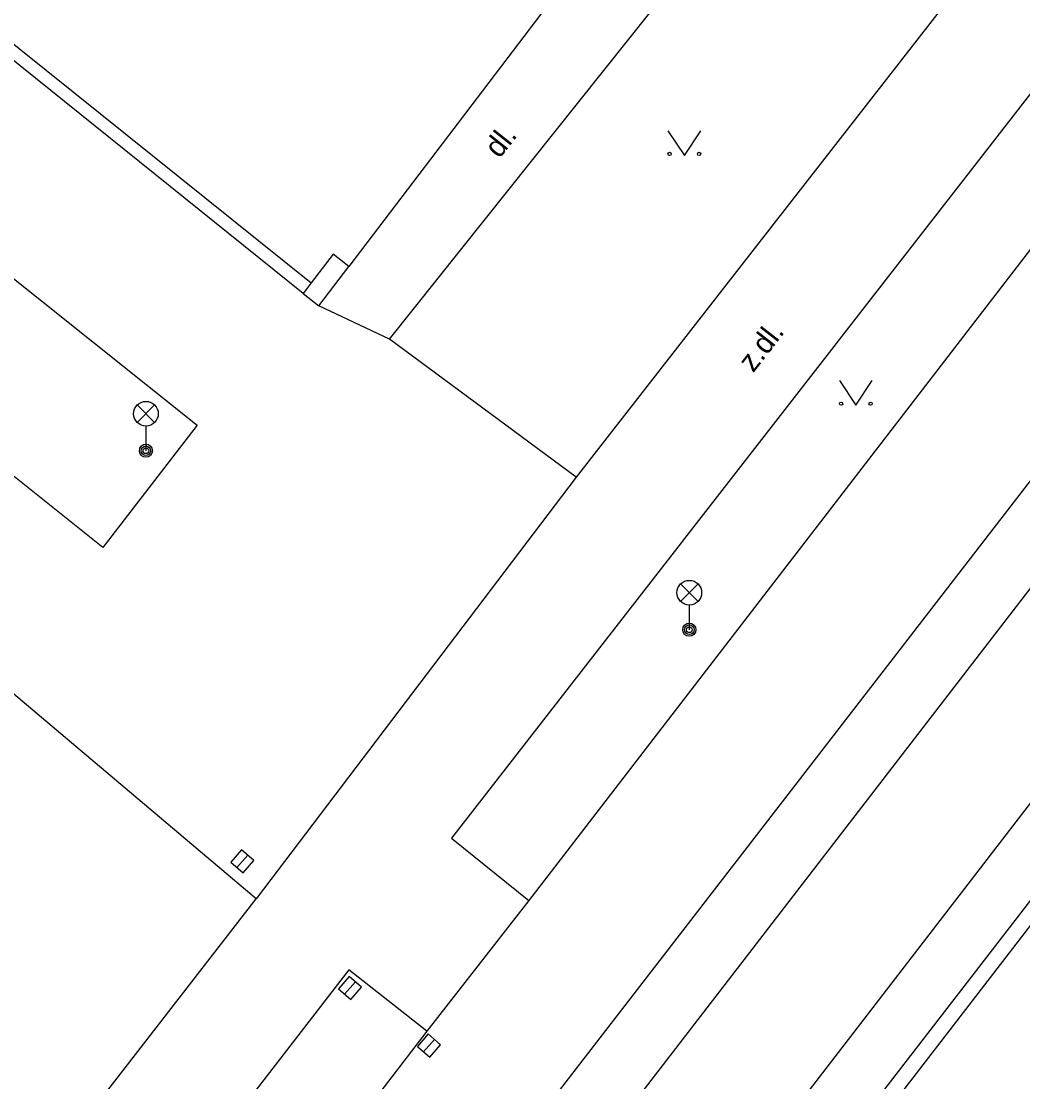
# Model space of a CAD drawing. Extents: x -598932 to -598196, y -1162207 to -1161504.
# Drawn here: x -598777.34 to -598746.91, y -1161970.82 to -1161938.58 of the extents above; entities that cross this region are included whole.
import ezdxf

# ---------------------------------------------------------------- set-up
doc = ezdxf.new("R2010")
doc.units = 0
for name, color, linetype in [('Level 27', 7, 'Continuous'), ('Level 33', 7, 'Continuous'), ('Level 36', 7, 'Continuous'), ('TM - chodniky - VP', 7, 'Continuous'), ('TM - komunikace - VP', 7, 'Continuous'), ('TM - MHD - osa koleji', 7, 'Continuous'), ('TM - popis povrchu', 7, 'Continuous'), ('TM - rozhrani ploch obecne - VP', 7, 'Continuous'), ('TM - zabradli - VP', 7, 'Continuous')]:
    doc.layers.add(name, color=color, linetype=linetype)

msp = doc.modelspace()

# ---------------------------------------------------------------- linework, layer by layer
at = {"layer": 'Level 27'}
for p, q in [((-598770.785, -1161964.308), (-598770.455, -1161963.932)), ((-598767.515, -1161968.158), (-598767.185, -1161967.782)), ((-598765.115, -1161969.908), (-598764.785, -1161969.532))]:
    msp.add_line(p, q, dxfattribs=at)
for points in [[(-598770.596, -1161964.473), (-598770.267, -1161964.096), (-598770.644, -1161963.767), (-598770.973, -1161964.144)], [(-598767.326, -1161968.323), (-598766.997, -1161967.946), (-598767.374, -1161967.617), (-598767.703, -1161967.994)], [(-598764.926, -1161970.073), (-598764.597, -1161969.696), (-598764.974, -1161969.367), (-598765.303, -1161969.744)]]:
    msp.add_lwpolyline(points, close=True, dxfattribs=at)
at = {"layer": 'Level 33'}
for p, q in [((-598773.815, -1161950.78), (-598773.285, -1161950.25)), ((-598773.815, -1161950.25), (-598773.285, -1161950.78)), ((-598773.55, -1161950.89), (-598773.55, -1161951.64)), ((-598757.305, -1161956.22), (-598756.775, -1161955.69)), ((-598757.305, -1161955.69), (-598756.775, -1161956.22)), ((-598757.04, -1161956.33), (-598757.04, -1161957.08))]:
    msp.add_line(p, q, dxfattribs=at)
for centre, radius in [((-598773.55, -1161950.515), 0.375), ((-598773.55, -1161951.64), 0.2), ((-598773.55, -1161951.64), 0.145), ((-598773.55, -1161951.64), 0.0876), ((-598757.04, -1161955.955), 0.375), ((-598757.04, -1161957.08), 0.2), ((-598757.04, -1161957.08), 0.145), ((-598757.04, -1161957.08), 0.0876)]:
    msp.add_circle(centre, radius, dxfattribs=at)
at = {"layer": 'Level 36'}
for points in [[(-598757.69, -1161941.92), (-598757.19, -1161942.67), (-598756.69, -1161941.92)], [(-598752.48, -1161949.51), (-598751.98, -1161950.26), (-598751.48, -1161949.51)]]:
    msp.add_lwpolyline(points, dxfattribs=at)
for centre in [(-598757.64, -1161942.62), (-598756.741, -1161942.62), (-598752.43, -1161950.21), (-598751.531, -1161950.21)]:
    msp.add_circle(centre, 0.05, dxfattribs=at)
at = {"layer": 'TM - chodniky - VP'}
for points in [[(-598768.77, -1161946.86), (-598791.37, -1161928.67)], [(-598755.69, -1161930.65), (-598767.39, -1161946.04)], [(-598766.15, -1161948.25), (-598753.16, -1161931.96)], [(-598747.66, -1161935.98), (-598760.48, -1161952.44)], [(-598787.7, -1161938.32), (-598771.99, -1161950.86), (-598774.86, -1161954.58), (-598791.02, -1161941.65)], [(-598745.57, -1161939.36), (-598764.27, -1161963.42), (-598761.92, -1161965.31)], [(-598770.2, -1161965.26), (-598793.43, -1161945.64)], [(-598767.39, -1161946.04), (-598767.86, -1161945.67), (-598768.53, -1161946.54)], [(-598768.53, -1161946.54), (-598768.77, -1161946.86)], [(-598760.48, -1161952.44), (-598766.15, -1161948.25)], [(-598781.28, -1161979.55), (-598770.2, -1161965.26)], [(-598765.02, -1161969.28), (-598767.38, -1161967.42), (-598778.8, -1161982.18)]]:
    msp.add_lwpolyline(points, dxfattribs=at)
at = {"layer": 'TM - komunikace - VP'}
for points in [[(-598732.18, -1161933.2), (-598734.553, -1161936.682), (-598741.73, -1161946.14), (-598773.73, -1161987.57)], [(-598767.95, -1161993.7), (-598752.59, -1161973.75), (-598735.91, -1161952.1), (-598727.932, -1161941.857), (-598725.71, -1161939.09)], [(-598742.05, -1161939.52), (-598761.92, -1161965.31)], [(-598761.92, -1161965.31), (-598765.02, -1161969.28)], [(-598765.02, -1161969.28), (-598776.65, -1161984.47)]]:
    msp.add_lwpolyline(points, dxfattribs=at)
at = {"layer": 'TM - MHD - osa koleji'}
for points in [[(-598730.32, -1161934.63), (-598740.06, -1161947.23), (-598772.31, -1161989.08)], [(-598727.63, -1161937.65), (-598737.71, -1161950.7), (-598769.53, -1161992.03)]]:
    msp.add_lwpolyline(points, dxfattribs=at)
at = {"layer": 'TM - rozhrani ploch obecne - VP'}
for points in [[(-598768.31, -1161993.32), (-598736.23, -1161951.8), (-598728.355, -1161941.527), (-598726.2, -1161938.72)], [(-598768.3, -1161947.24), (-598767.39, -1161946.04)], [(-598768.77, -1161946.86), (-598768.3, -1161947.24)], [(-598766.15, -1161948.25), (-598768.3, -1161947.24)], [(-598760.48, -1161952.44), (-598770.2, -1161965.26)]]:
    msp.add_lwpolyline(points, dxfattribs=at)
at = {"layer": 'TM - zabradli - VP'}
msp.add_lwpolyline([(-598791.11, -1161928.41), (-598768.53, -1161946.54)], dxfattribs=at)

# ---------------------------------------------------------------- texts
at = {"layer": 'TM - popis povrchu'}
for s, rotation, p in [('dl.', 51.63, (-598762.81, -1161942.78)), ('z.dl.', 52.14, (-598755.1, -1161949.29))]:
    msp.add_text(s, height=0.65, rotation=rotation, dxfattribs=at).set_placement(p)

doc.saveas('drawing.dxf')
